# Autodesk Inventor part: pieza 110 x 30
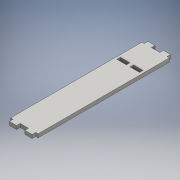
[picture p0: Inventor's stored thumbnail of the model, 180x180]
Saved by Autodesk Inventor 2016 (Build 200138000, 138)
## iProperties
Created: 2016-06
Part Number: pieza 110 x 30
Material: Genérico
Document SubType Name: Modeling
Designer: adm
Density: 1 g/cm^3
Appearance: Valor por defecto
Author: adm
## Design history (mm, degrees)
sketch "Boceto1"
  geometry: 1 further point
sketch "Boceto2"
  geometry: L1 (0, 0)-(0, 110); L2 (0, 110)-(2, 110); L3 (2, 110)-(2, 113); L4 (2, 113)-(8, 113); L5 (8, 113)-(8, 110); L6 (8, 110)-(15, 110); L7 (15, 110)-(15, 113); L8 (15, 113)-(21, 113); L9 (21, 113)-(21, 110); L10 (21, 110)-(23, 110); L11 (23, 110)-(23, 0); L12 (23, 0)-(21, 0); L13 (21, 0)-(21, -3); L14 (21, -3)-(15, -3); L15 (15, -3)-(15, 0); L16 (15, 0)-(8, 0); L17 (8, 0)-(8, -3); L18 (8, -3)-(2, -3); L19 (2, -3)-(2, 0); L20 (2, 0)-(0, 0); L21 (2, 90)-(2, 87); L22 (2, 87)-(10, 87); L23 (10, 87)-(10, 90); L24 (10, 90)-(2, 90); L25 (21, 90)-(21, 87); L26 (21, 87)-(15, 87); L27 (15, 87)-(13, 87); L28 (13, 87)-(13, 90); L29 (13, 90)-(21, 90)
  constraints: 58 end point, 12 point on line, 10 perpendicular, 2 horizontal, 1 vertical
extrude "Extrusión1" new body sketch "Boceto2" distance "d28" = 3; taper "d29" = 0 deg
node "Sólido1"
